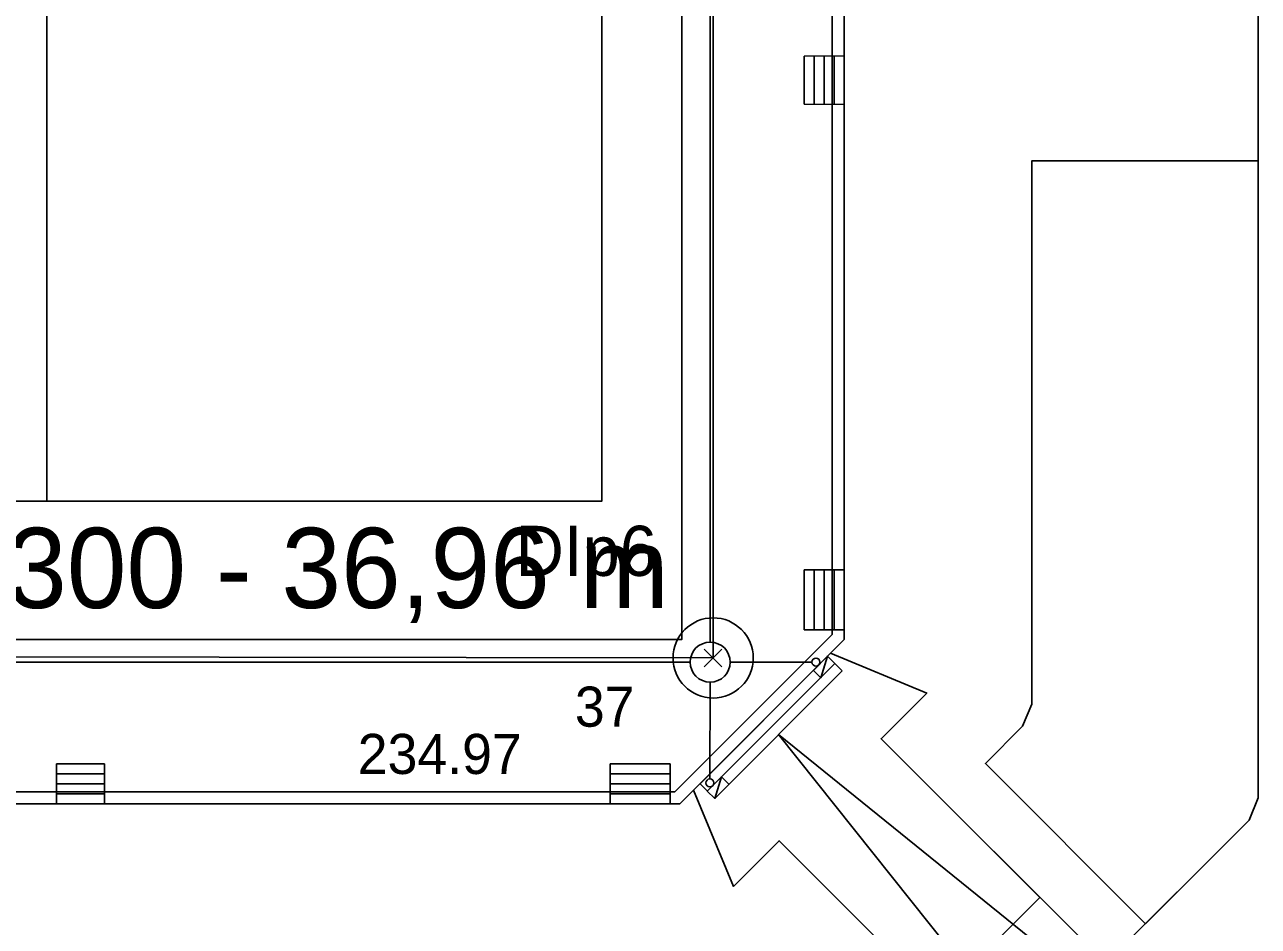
# Model space of a CAD drawing. Extents: x -264234 to -263604, y -1242346 to -1242049.
# Drawn here: x -263832.36 to -263801.59, y -1242227.48 to -1242205 of the extents above; entities that cross this region are included whole.
import ezdxf

# ---------------------------------------------------------------- set-up
doc = ezdxf.new("R2010")
doc.units = 0
for name, color, linetype in [('KFA_BODY_CISLO', 7, 'Continuous'), ('KFA_BODY_SYMBOL', 7, 'Continuous'), ('KFA_BODY_VYSKA', 7, 'Continuous'), ('KFA_DAZDOVA_KANALIZACIA_vetva_I', 7, 'Continuous'), ('KFA_DAZDOVA_KANALIZACIA_vetva_I_popis', 7, 'Continuous'), ('KFA_SITUACIA_DSP', 7, 'Continuous')]:
    doc.layers.add(name, color=color, linetype=linetype)

msp = doc.modelspace()

# ---------------------------------------------------------------- linework, layer by layer
at = {"layer": 'KFA_BODY_SYMBOL'}
for p, q in [((-263815.41, -1242221.012), (-263814.968, -1242220.57)), ((-263814.968, -1242221.012), (-263815.41, -1242220.57))]:
    msp.add_line(p, q, dxfattribs=at)
at = {"layer": 'KFA_DAZDOVA_KANALIZACIA_vetva_I'}
msp.add_lwpolyline([(-263814.907, -1242107.856), (-263815.198, -1242164.443), (-263815.189, -1242220.791), (-263852.152, -1242220.736), (-263888.701, -1242220.786), (-263906.731, -1242239.259)], dxfattribs=at)
msp.add_circle((-263815.189, -1242220.791), 1, dxfattribs=at)
at = {"layer": 'KFA_SITUACIA_DSP'}
for p, q in [((-263815.263, -1242164.687), (-263815.263, -1242220.396)), ((-263811.924, -1242205.773), (-263812.918, -1242205.782)), ((-263812.918, -1242205.782), (-263812.918, -1242206.982)), ((-263812.668, -1242205.782), (-263812.668, -1242206.982)), ((-263812.418, -1242205.782), (-263812.418, -1242206.982)), ((-263812.168, -1242205.782), (-263812.168, -1242206.982)), ((-263812.918, -1242206.982), (-263811.924, -1242206.991)), ((-263807.243, -1242208.394), (-263807.243, -1242221.942)), ((-263801.593, -1242208.394), (-263807.243, -1242208.394)), ((-263801.593, -1242224.282), (-263801.593, -1242208.394)), ((-263811.939, -1242218.592), (-263812.918, -1242218.592)), ((-263812.918, -1242218.592), (-263812.918, -1242220.092)), ((-263812.668, -1242218.592), (-263812.668, -1242220.092)), ((-263812.418, -1242218.592), (-263812.418, -1242220.092)), ((-263812.168, -1242218.592), (-263812.168, -1242220.092)), ((-263812.918, -1242220.092), (-263811.918, -1242220.092)), ((-263815.516, -1242223.929), (-263812.335, -1242220.747)), ((-263812.506, -1242221.283), (-263812.335, -1242220.747)), ((-263812.151, -1242220.931), (-263812.335, -1242220.747)), ((-263851.668, -1242220.896), (-263815.763, -1242220.896)), ((-263815.334, -1242224.112), (-263812.152, -1242220.929)), ((-263811.968, -1242221.113), (-263815.15, -1242224.295)), ((-263812.725, -1242220.896), (-263814.763, -1242220.896)), ((-263812.504, -1242221.284), (-263812.688, -1242221.101)), ((-263811.968, -1242221.113), (-263812.152, -1242220.929)), ((-263815.27, -1242223.809), (-263815.264, -1242221.396)), ((-263807.243, -1242221.942), (-263807.472, -1242222.496)), ((-263807.472, -1242222.496), (-263808.4, -1242223.424)), ((-263830.369, -1242223.432), (-263831.567, -1242223.432)), ((-263831.567, -1242223.432), (-263831.567, -1242224.432)), ((-263830.369, -1242224.432), (-263830.369, -1242223.432)), ((-263816.259, -1242223.432), (-263817.757, -1242223.432)), ((-263817.757, -1242223.432), (-263817.757, -1242224.432)), ((-263816.259, -1242224.432), (-263816.259, -1242223.432)), ((-263808.4, -1242223.424), (-263804.405, -1242227.419)), ((-263830.369, -1242223.682), (-263831.567, -1242223.682)), ((-263816.259, -1242223.682), (-263817.757, -1242223.682)), ((-263815.333, -1242224.113), (-263815.516, -1242223.929)), ((-263815.15, -1242224.295), (-263814.98, -1242223.758)), ((-263814.797, -1242223.942), (-263814.98, -1242223.758)), ((-263830.369, -1242223.932), (-263831.567, -1242223.932)), ((-263830.369, -1242224.182), (-263831.567, -1242224.182)), ((-263816.259, -1242223.932), (-263817.757, -1242223.932)), ((-263816.259, -1242224.182), (-263817.757, -1242224.182)), ((-263815.15, -1242224.295), (-263815.334, -1242224.112)), ((-263801.822, -1242224.837), (-263801.593, -1242224.282)), ((-263804.405, -1242227.419), (-263801.822, -1242224.837))]:
    msp.add_line(p, q, dxfattribs=at)
for points in [[(-263909.043, -1242125.432), (-263902.343, -1242125.432), (-263902.343, -1242104.482), (-263902.112, -1242103.927), (-263898.54, -1242100.355), (-263895.995, -1242097.81), (-263892.423, -1242094.238), (-263891.868, -1242094.007), (-263812.071, -1242094.007), (-263811.513, -1242094.238), (-263801.823, -1242103.927), (-263801.593, -1242104.482), (-263801.593, -1242224.282), (-263801.824, -1242224.838), (-263805.392, -1242228.407)], [(-263811.918, -1242108.434), (-263811.918, -1242220.33), (-263812.262, -1242220.675), (-263809.862, -1242221.669), (-263810.999, -1242222.806), (-263807.039, -1242226.765), (-263809.585, -1242229.311), (-263813.545, -1242225.351), (-263814.681, -1242226.488), (-263815.675, -1242224.088), (-263816.02, -1242224.432), (-263887.916, -1242224.432), (-263888.26, -1242224.088), (-263889.254, -1242226.488), (-263890.391, -1242225.351), (-263894.351, -1242229.311), (-263896.896, -1242226.765), (-263892.937, -1242222.806), (-263894.073, -1242221.669), (-263891.673, -1242220.675), (-263892.018, -1242220.33), (-263892.018, -1242181.432), (-263893.618, -1242181.432), (-263893.618, -1242147.332)], [(-263807.941, -1242230.956), (-263813.544, -1242225.352), (-263814.681, -1242226.488), (-263815.675, -1242224.088), (-263812.262, -1242220.675)], [(-263812.262, -1242220.675), (-263809.863, -1242221.669), (-263810.999, -1242222.806), (-263805.392, -1242228.407)], [(-263803.204, -1242235.693), (-263813.559, -1242222.704), (-263800.652, -1242233.141)]]:
    msp.add_lwpolyline(points, dxfattribs=at)
for points in [[(-263816.02, -1242224.432), (-263811.918, -1242220.33), (-263811.918, -1242108.434), (-263816.02, -1242104.332), (-263887.916, -1242104.332), (-263892.018, -1242108.434), (-263892.018, -1242147.332), (-263893.618, -1242147.332), (-263893.618, -1242162.382), (-263894.718, -1242162.382), (-263894.718, -1242166.382), (-263893.618, -1242166.382), (-263893.618, -1242181.432), (-263892.018, -1242181.432), (-263892.018, -1242220.33), (-263887.916, -1242224.432)], [(-263816.144, -1242224.132), (-263812.218, -1242220.206), (-263812.218, -1242108.558), (-263816.144, -1242104.632), (-263887.792, -1242104.632), (-263891.718, -1242108.558), (-263891.718, -1242147.632), (-263893.318, -1242147.632), (-263893.318, -1242162.682), (-263894.418, -1242162.682), (-263894.418, -1242166.082), (-263893.318, -1242166.082), (-263893.318, -1242181.132), (-263891.718, -1242181.132), (-263891.718, -1242220.206), (-263887.792, -1242224.132)], [(-263887.968, -1242108.434), (-263815.968, -1242108.434), (-263815.968, -1242220.33), (-263887.968, -1242220.33)], [(-263885.968, -1242111.882), (-263817.968, -1242111.882), (-263817.968, -1242216.882), (-263885.968, -1242216.882)], [(-263831.808, -1242200.382), (-263872.128, -1242200.382), (-263872.128, -1242216.882), (-263831.808, -1242216.882)], [(-263801.593, -1242208.394), (-263807.243, -1242208.394), (-263807.243, -1242221.942), (-263807.472, -1242222.496), (-263808.4, -1242223.424), (-263804.405, -1242227.419), (-263801.822, -1242224.837), (-263801.593, -1242224.282)], [(-263812.688, -1242221.101), (-263812.506, -1242221.283), (-263812.335, -1242220.747)], [(-263814.98, -1242223.758), (-263815.334, -1242224.112), (-263815.15, -1242224.295)]]:
    msp.add_lwpolyline(points, close=True, dxfattribs=at)
for centre, radius in [((-263815.263, -1242220.896), 0.5), ((-263812.625, -1242220.896), 0.1), ((-263815.27, -1242223.909), 0.1)]:
    msp.add_circle(centre, radius, dxfattribs=at)

# ---------------------------------------------------------------- texts
at = {"layer": 'KFA_BODY_CISLO'}
msp.add_text('37', height=1, dxfattribs=at).set_placement((-263818.637, -1242222.506))
at = {"layer": 'KFA_BODY_VYSKA'}
msp.add_text('234.97', height=1, dxfattribs=at).set_placement((-263824.052, -1242223.685))
at = {"layer": 'KFA_DAZDOVA_KANALIZACIA_vetva_I_popis'}
for s, height, p in [('I2, PVC DN300 - 36,96 m', 2, (-263846.616, -1242219.546)), ('DIp6', 1.25, (-263820.118, -1242218.745))]:
    msp.add_text(s, height=height, dxfattribs=at).set_placement(p)

doc.saveas('drawing.dxf')
